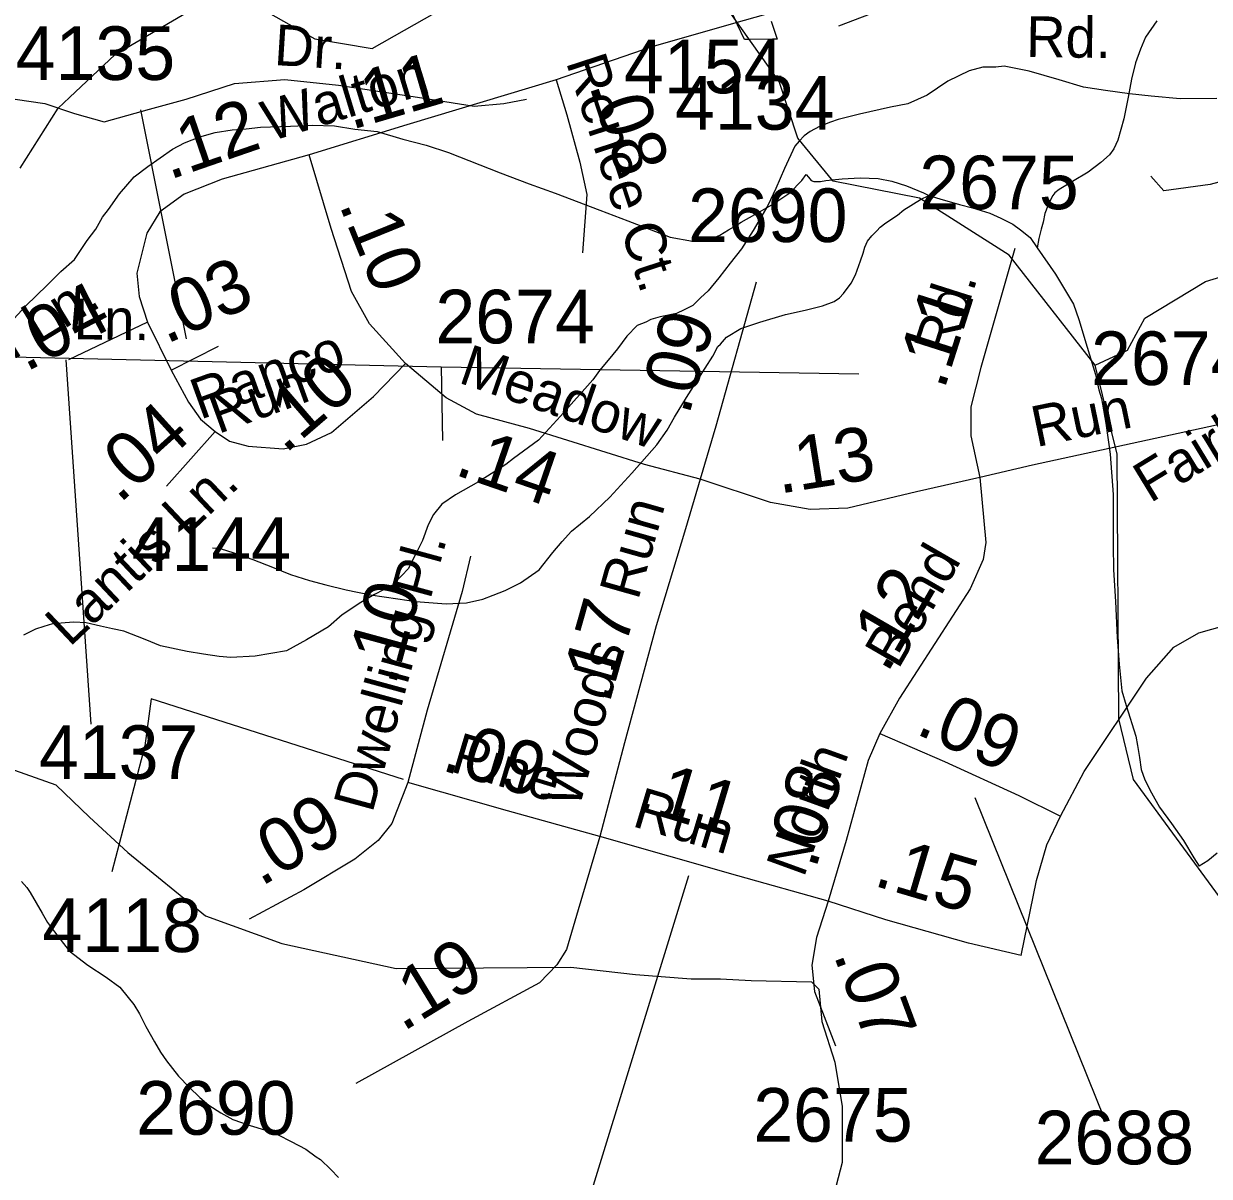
# Model space of a CAD drawing. Extents: x 2169602 to 2449496, y 721995 to 810662.
# Drawn here: x 2398160 to 2400925, y 794793 to 797480 of the extents above; entities that cross this region are included whole.
import ezdxf

# ---------------------------------------------------------------- set-up
doc = ezdxf.new("R2010")
doc.units = 0
doc.layers.add('Default', color=7, linetype='Continuous')

msp = doc.modelspace()

# ---------------------------------------------------------------- linework, layer by layer
at = {"layer": 'Default'}
for p, q in [((2398539.8, 796745.2), (2398433, 797279.2)), ((2397196.1, 796724.9), (2399133.5, 796680.2)), ((2398258.2, 796696.7), (2398316.5, 795847.2)), ((2400378.4, 795676.5), (2400680.4, 794926.3)), ((2399710.5, 795493.6), (2399326.2, 794249.2))]:
    msp.add_line(p, q, dxfattribs=at)
for points in [[(2398266.3, 797307.9), (2398373, 797408.5), (2398605.1, 797544.9), (2398705, 797519.8), (2398839.1, 797444.9), (2398972.2, 797422.5), (2399147.1, 797520.7), (2399338, 797556.1), (2399504.1, 797674.1), (2399686.2, 797942.7), (2399826, 798251.5), (2400025.1, 798427.8), (2400174, 798503.5), (2400406.1, 798761.2), (2400505.2, 798946.2), (2400662, 799103.7), (2400836.1, 799398.6), (2400883.4, 799504.9)], [(2400658.9, 796684.1), (2400457.9, 796940.8), (2400249, 797073), (2400048, 797113.2), (2399965, 797213.3), (2399921.9, 797345.4), (2399721, 797628.4), (2399577, 797952.9), (2399568, 798103.9), (2399432, 798592.2), (2399421, 799094.3)], [(2401076, 797995), (2401022.2, 797916.5), (2400976.2, 797854.1), (2400879.3, 797790.9), (2400754.9, 797754.7), (2400429.4, 797653.6), (2399840.3, 797487.1), (2399624.7, 797426.4), (2399401.8, 797348.9)], [(2400409.8, 797609.5), (2400303.8, 797567.7), (2400060.4, 797474)], [(2399903, 797486.2), (2399917, 797443.7), (2399906.5, 797443.6), (2399854, 797442.9), (2399841, 797443.1), (2399825, 797477.7), (2399792.2, 797551.2)], [(2399903, 797486.2), (2399917, 797443.7), (2399906.5, 797443.6), (2399854, 797442.9), (2399841, 797443.1), (2399825, 797477.7), (2399792.2, 797551.2)], [(2400802.6, 797486.7), (2400776.6, 797448.9), (2400764.7, 797420.6), (2400753, 797388.8), (2400743.3, 797350.5), (2400735.6, 797308.7), (2400725.9, 797258.6), (2400712, 797208.4), (2400702.3, 797188.4), (2400692.3, 797174.4), (2400672.2, 797156.4), (2400642.7, 797134.1), (2400606.2, 797112), (2400574.8, 797093.6), (2400565, 797085.8), (2400560.4, 797079.6), (2400554.5, 797069.5), (2400548.8, 797055.4)], [(2400942.9, 797305.6), (2400857, 797305.2), (2400789.2, 797311), (2400739.1, 797316.6), (2400683.1, 797324.2), (2400631.3, 797332.1), (2400575.1, 797349.5), (2400504.7, 797369), (2400446.9, 797381.1), (2400427, 797378.8), (2400396.7, 797378.5), (2400365.1, 797370.3), (2400315.3, 797346.2), (2400267.3, 797313.7), (2400221.6, 797293.5), (2400181.4, 797285.3), (2400109.4, 797269), (2400059.8, 797256.7), (2400041.7, 797250.4), (2400015.9, 797240.6), (2399994, 797228.5), (2399979.8, 797218.4), (2399968.1, 797206.4), (2399958.1, 797194.2), (2399934.5, 797142.1), (2399914.4, 797096.1), (2399895.1, 797056), (2399861.1, 796997.9), (2399833.6, 796955.4), (2399807.6, 796921.6), (2399781.5, 796887.4), (2399756.1, 796857.2), (2399738.1, 796840.8), (2399720.2, 796822.9), (2399700.3, 796812.9), (2399682.3, 796804.6), (2399644.6, 796796.6), (2399622.6, 796790.6), (2399610.5, 796784.3), (2399590.6, 796776.3), (2399566.8, 796751.9), (2399544.9, 796722), (2399523.2, 796695.7), (2399502.9, 796671.5), (2399487.5, 796649.5), (2399411.8, 796565.3), (2399360.4, 796509), (2399302.3, 796466.6), (2399284.7, 796452.6), (2399256.6, 796434.6), (2399220.9, 796412), (2399167, 796382), (2399134.8, 796359.7), (2399115.5, 796335.5)], [(2397390.5, 797368.8), (2397476.7, 797327), (2397565.3, 797272.8), (2397612.1, 797258), (2397697.9, 797234.7), (2397813.4, 797238), (2397951.9, 797277.6), (2398050.9, 797297.5), (2398140, 797304.1), (2398209.2, 797294.1), (2398278.5, 797271), (2398347.8, 797251.2), (2398453.3, 797280.9), (2398539.1, 797304.1), (2398651.3, 797340.4), (2398768.7, 797350.3), (2398894, 797337.1), (2399088.7, 797307.4), (2399210.7, 797287.5), (2399280, 797294.1), (2399332.8, 797304.1)], [(2399401.8, 797348.9), (2399053.4, 797244.2), (2398825.3, 797174.1)], [(2399401.8, 797348.9), (2399426.4, 797267.2), (2399456.8, 797157.3), (2399473.5, 797081.9), (2399463, 796945.8)], [(2402253.8, 797323.8), (2402181.6, 797267.2), (2402069.6, 797203.4), (2401921, 797151), (2401586.7, 797054.7), (2401406.7, 797006.5), (2401343.9, 796991.9), (2401295.8, 796997.1), (2401285.3, 797032.7), (2401278, 797117.5), (2401271.7, 797156.3), (2401253.9, 797181.4), (2401225.7, 797179.3), (2401168.1, 797169.9), (2400926.9, 797104.9), (2400819.2, 797090.3), (2400788.8, 797124.8)], [(2398151.3, 797143.3), (2398240.2, 797283.3), (2398266.3, 797307.9)], [(2398127.1, 796782), (2398164.8, 796822.1), (2398214.6, 796870.5), (2398246.2, 796902.6), (2398278.2, 796930.7), (2398307.9, 796974.9), (2398328, 797001), (2398343.8, 797029), (2398357.8, 797047.2), (2398383.4, 797083.1), (2398417.2, 797123.4), (2398449, 797147.4), (2398506.6, 797187.8), (2398534.5, 797202.2), (2398570.4, 797216.3), (2398606.5, 797226.2), (2398646.3, 797232.8), (2398678.5, 797234.8), (2398712.3, 797239), (2398782.4, 797241.4), (2398832.5, 797243.5), (2398884.6, 797242.1), (2398932.5, 797234.1), (2398984.4, 797228.7), (2399044.3, 797211.1), (2399098.6, 797197.2), (2399150.9, 797179.6), (2399270.9, 797132.2), (2399338.9, 797106.6), (2399399.4, 797084.8), (2399503.4, 797045.5), (2399569.2, 797020.2), (2399667.6, 796982.6), (2399719.9, 796972.7), (2399739.4, 796972.9), (2399765.7, 796979.1), (2399783.5, 796987), (2399793.3, 796993.2), (2399803.4, 796999.4), (2399817.5, 797007.4), (2399833.5, 797017.5), (2399865.1, 797035.5), (2399904.9, 797057.9), (2399946.9, 797085.9), (2399974.6, 797114.2), (2399984.7, 797128.5)], [(2398825.3, 797174.1), (2398622.8, 797117.5), (2398533.9, 797083), (2398477.3, 797041.1), (2398447, 796991.9), (2398424, 796898.7), (2398429.2, 796844.2), (2398448.6, 796784.5)], [(2399050.2, 796688.2), (2398966, 796780.3), (2398924.2, 796855.7), (2398877.1, 797002.3), (2398825.3, 797174.1)], [(2399984.7, 797128.5), (2399990.4, 797122.4), (2399996.8, 797114.5), (2400002.9, 797112.4), (2400018.5, 797112.4), (2400030.8, 797114.7), (2400068.9, 797118.6), (2400111, 797120.8), (2400152.8, 797119.3), (2400184.8, 797113.3), (2400218.6, 797101.7), (2400258.4, 797085.9), (2400271.1, 797079.9)], [(2398600.1, 796258.5), (2398618, 796256.6), (2398650, 796246.9), (2398694.1, 796231.3), (2398740, 796213.4), (2398782.2, 796195.7), (2398826.7, 796182.1), (2398864.5, 796172.3), (2398912.2, 796160.6), (2398968.6, 796148.9), (2399032.4, 796139.2), (2399074.4, 796133.3), (2399144.8, 796127.9), (2399192.3, 796130), (2399230.3, 796138.5), (2399254.5, 796148.2), (2399282.6, 796158.5), (2399318.2, 796176.7), (2399361.9, 796207), (2399393.7, 796247.2), (2399415.4, 796273.1), (2399437.4, 796297.4), (2399479.2, 796331.6), (2399527, 796376), (2399578.4, 796432.2), (2399636.7, 796498.5), (2399660.3, 796532.7), (2399677.9, 796562.8), (2399705.6, 796608.9), (2399727.5, 796642.9), (2399749.3, 796677), (2399767.1, 796705.1), (2399778.8, 796727.3), (2399784.9, 796733.2), (2399798.7, 796749.4), (2399832.7, 796769.4), (2399876.8, 796783.9), (2399936.3, 796802), (2399982.6, 796812.5), (2400022.6, 796822.6), (2400050.1, 796832.7), (2400062.2, 796841), (2400072.2, 796850.8), (2400089.8, 796874.9), (2400100.1, 796894.9), (2400111.8, 796927.2), (2400117.7, 796944.9), (2400121.4, 796959), (2400127.6, 796973.1), (2400137.6, 796985.3), (2400149.3, 796997.4), (2400157.1, 797005.5), (2400171, 797015.6), (2400197.5, 797033.5), (2400212.7, 797045.8), (2400251.2, 797070), (2400271.1, 797079.9)], [(2400271.1, 797079.9), (2400296.9, 797071.9), (2400342.7, 797058.6), (2400372.8, 797050.4), (2400413, 797038.6), (2400439.1, 797026.9), (2400466.9, 797013), (2400485, 796999.3), (2400507.1, 796981.4), (2400523.5, 796957.4)], [(2400548.8, 797055.4), (2400541.2, 797037.5), (2400537.3, 797017.4), (2400533, 797001.4), (2400527.2, 796979.5), (2400523.5, 796957.4)], [(2400658.9, 796684.1), (2400733.9, 796718.6), (2400774.9, 796793.3), (2400916, 796878.9), (2401107.9, 796937.3), (2401167.1, 797030.5)], [(2402601.2, 796979.3), (2402525.8, 796917.5), (2402428.5, 796865.2), (2402260, 796817), (2401715.4, 796707), (2401138.8, 796586.6), (2400512.6, 796450.5), (2400389.6, 796422.2)], [(2400471.8, 796956.3), (2400392.2, 796678.8), (2400369.2, 796586.6), (2400369.2, 796519.6), (2400389.6, 796422.2)], [(2400523.5, 796957.4), (2400566, 796895.8), (2400594.1, 796849.8), (2400608.4, 796826.1), (2400620.7, 796790.2), (2400640.6, 796726.3), (2400659.3, 796662.3), (2400667.3, 796626.2)], [(2399868.5, 796877.7), (2399773.8, 796541.6), (2399737.7, 796418)], [(2398448.6, 796784.5), (2398264.4, 796696.6)], [(2398448.6, 796784.5), (2398504, 796672.5)], [(2398504, 796672.5), (2398613.9, 796728)], [(2398606.1, 796529), (2398639.5, 796507), (2398683.5, 796495.5), (2398765.1, 796489.2), (2398819.5, 796499.7), (2398878.1, 796526.9), (2398975.4, 796610.7), (2399050.2, 796688.2)], [(2399737.7, 796418), (2399607.4, 796452.6), (2399339.6, 796536.4), (2399215.6, 796569.9), (2399145.5, 796607.6), (2399050.2, 796688.2)], [(2398504, 796672.5), (2398543.8, 796598.1), (2398572, 796558.3), (2398606.1, 796529)], [(2399133.5, 796680.2), (2399136.8, 796508.5)], [(2399133.5, 796680.2), (2400107.3, 796663.7)], [(2401167.1, 794204.8), (2401155.9, 794220.1), (2401029, 794652.5), (2400986.9, 794702.5), (2401000.9, 795086.1), (2400949, 795444.7), (2400747.9, 795717.8), (2400714, 795859.6), (2400709.9, 796476.4), (2400658.9, 796684.1)], [(2400667.3, 796626.2), (2400673.4, 796606.6), (2400683.7, 796548.6), (2400694.1, 796476.5), (2400700.7, 796382.6), (2400701.1, 796310.7), (2400700.9, 796264.5), (2400701.5, 796206.8), (2400706.2, 796132.7), (2400710.5, 796048.9), (2400714.6, 795987), (2400721.4, 795924.7), (2400731.5, 795890.8), (2400753.8, 795819.2), (2400757.9, 795797.1), (2400762.2, 795769.3), (2400765.9, 795741.2), (2400774.7, 795717.1), (2400790.5, 795687.1), (2400808.8, 795653.6), (2400836.9, 795615.6), (2400864.9, 795575.7), (2400889.3, 795535.9), (2400901.4, 795516.2)], [(2398606.1, 796529), (2398493, 796402.3)], [(2399737.7, 796418), (2399703.2, 796302.8), (2399634.6, 796076.7), (2399561.4, 795803.4), (2399503.3, 795585.6)], [(2400389.6, 796422.2), (2400242.1, 796388.7), (2400082, 796351), (2399994.1, 796347.9), (2399902, 796363.6), (2399737.7, 796418)], [(2400389.6, 796422.2), (2400403.7, 796270.4), (2400397.5, 796230.6), (2400367.1, 796162.5), (2400202.3, 795908.1), (2400156.8, 795825.4)], [(2399115.5, 796335.5), (2399103.4, 796311.7), (2399089.9, 796275.6), (2399075.7, 796247.3), (2399056.3, 796209.3), (2399042.1, 796193.3), (2399020.2, 796171), (2398978.1, 796149), (2398946.1, 796130.7), (2398902.9, 796102.3), (2398870.9, 796074.3), (2398819.2, 796044), (2398773.1, 796017.7), (2398699.3, 796005.3), (2398643.1, 796002.9), (2398615.4, 796005), (2398579.5, 796010.5), (2398541.4, 796016.6), (2398479, 796030.1), (2398443.2, 796044.1), (2398393.3, 796063.8), (2398366.9, 796069.4), (2398338.6, 796075.3), (2398305.2, 796083.2), (2398276.9, 796085), (2398226.8, 796080.8), (2398207.1, 796074.5), (2398187, 796068.6), (2398159.2, 796054.2)], [(2399202, 796239), (2399182.1, 796156.2), (2399101, 795879.8), (2399056, 795711.2)], [(2400578, 795632.7), (2400633.4, 795736.4), (2400778.9, 795954.2), (2400842.7, 796026.4), (2400900.8, 796059.9), (2401041, 796099.7), (2401394.7, 796166.7), (2401631.7, 796218)], [(2399045.7, 795718.4), (2398457.4, 795906.3), (2398442.4, 795796.8), (2398365.1, 795502.5)], [(2400156.8, 795825.4), (2400129.1, 795762.5), (2400078.3, 795576.1), (2400035.9, 795434.8)], [(2400156.8, 795825.4), (2400307.5, 795760.4), (2400481.2, 795680.9), (2400578, 795632.7)], [(2398138.7, 795739.7), (2398234.6, 795705.4), (2398313.3, 795630.1), (2398402.3, 795547.9), (2398583.7, 795400.6), (2398761.7, 795335.5), (2399028.6, 795277.3)], [(2399056, 795711.2), (2399018.3, 795615.9), (2398986.9, 795576.1), (2398932.5, 795532.2), (2398813.2, 795461), (2398685.6, 795392.9)], [(2399503.3, 795585.6), (2399288.3, 795645.3), (2399056, 795711.2)], [(2400485.9, 795308.1), (2400522, 795482.9), (2400546.1, 795565.7), (2400578, 795632.7)], [(2399503.3, 795585.6), (2399448.9, 795401.3), (2399425.9, 795321.7), (2399402.9, 795286.1), (2399363.1, 795244.2), (2399195.7, 795154.1), (2398934.1, 795009.6)], [(2400035.9, 795434.8), (2399825.6, 795493.4), (2399503.3, 795585.6)], [(2400943.5, 795546.4), (2400921.3, 795528.2), (2400901.4, 795516.2)], [(2398154.8, 795480.1), (2398166.9, 795466.5), (2398174.7, 795454.4), (2398189, 795430.8), (2398202.8, 795406.8), (2398215.3, 795384.6), (2398231.3, 795362.7), (2398265.5, 795319), (2398309.6, 795285.1), (2398351.8, 795257.6), (2398384, 795233.7), (2398403.7, 795210), (2398416.4, 795193.9), (2398430.2, 795172), (2398444.3, 795142.3), (2398464.8, 795106.3), (2398478.5, 795082.3), (2398493.1, 795062.3), (2398521.2, 795026.4), (2398545.4, 795000.8), (2398571, 794976.7), (2398591.5, 794959), (2398619.6, 794941.4), (2398647.5, 794925.4), (2398687.7, 794911.6), (2398721.7, 794901.5), (2398753.7, 794889.8), (2398783.5, 794873.9), (2398817.9, 794856.2), (2398841.7, 794838.4), (2398851.7, 794832.4), (2398876.3, 794808.8), (2398894.2, 794790.7)], [(2400035.9, 795434.8), (2400009.3, 795350), (2399997.7, 795285), (2400004, 795224.3), (2400053.2, 795097.6)], [(2400485.9, 795308.1), (2400363.5, 795336.3), (2400170.9, 795390.8), (2400035.9, 795434.8)], [(2399028.6, 795277.3), (2399435.9, 795280.7), (2399586.5, 795263.6), (2399716.5, 795253.3), (2399785, 795253.3), (2399856.9, 795249.9), (2399997.2, 795246.5), (2400014.3, 795229.4), (2400021.2, 795154), (2400051.4, 795059), (2400068.6, 794955.5), (2400069.1, 794825.2), (2400045.1, 794736.2), (2400031.4, 794636.9), (2400041.7, 794530.7), (2400087.8, 794438.6), (2400099.7, 794382.4)]]:
    msp.add_lwpolyline(points, dxfattribs=at)

# ---------------------------------------------------------------- texts
for s, height, rotation, p in [('Rd.', 95, 359.1903, (2400497.4, 797402.6)), ('Dr.', 95, 356.4222, (2398742.3, 797383.8)), ('.11', 125, 16.3535, (2398923.5, 797232.1)), ('Renee Ct.', 95, 288.0547, (2399424.1, 797391)), ('Walton', 95, 16.9836, (2398733.4, 797204.6)), ('.08', 125, 288.0547, (2399477.9, 797336.7)), ('.12', 125, 19.0635, (2398499.2, 797115.5)), ('.10', 125, 292.1024, (2398894.6, 797058.6)), ('.03', 125, 24.1407, (2398491.8, 796732.2)), ('Rd.', 95, 72.3167, (2400324.7, 796698.5)), ('Fairbluff Ln.', 95, 31.3374, (2397771.1, 796474.1)), ('.04', 125, 27.1443, (2398164.5, 796667.2)), ('Ln.', 95, 359.2124, (2398276.2, 796744.5)), ('.11', 125, 72.3167, (2400306.5, 796623.9)), ('.09', 125, 74.4809, (2399711.2, 796564.5)), ('Ranco', 95, 19.9113, (2398571.2, 796556.4)), ('Fairbluff Ln.', 95, 31.3374, (2400787, 796361.3)), ('Meadow', 95, 340.9671, (2399171, 796644.2)), ('.10', 125, 40.7529, (2398769.2, 796475.4)), ('Run', 95, 19.9113, (2398613.2, 796523)), ('Run', 95, 11.6924, (2400521.4, 796492.7)), ('.04', 125, 42.0233, (2398382.9, 796359.4)), ('.13', 125, 9.0591, (2399922, 796384.1)), ('.14', 125, 340.9671, (2399161.4, 796429.9)), ('Lantis Ln.', 95, 43.3734, (2398266.7, 796025.3)), ('Run', 95, 74.138, (2399592.7, 796134)), ('Dwelling Pl.', 95, 74.7887, (2398972.9, 795638.1)), ('Bend', 95, 59.9405, (2400199.4, 795972.9)), ('.12', 125, 59.9405, (2400173.3, 795963)), ('.10', 125, 74.7887, (2399026.5, 795934.5)), ('.17', 125, 74.138, (2399525.1, 795891.6)), ('Woods', 95, 74.138, (2399454.3, 795646.9)), ('.09', 125, 336.4723, (2400236.7, 795826)), ('.09', 125, 343.2443, (2399131, 795740.8)), ('Pine', 95, 343.2443, (2399152, 795737.8)), ('North', 95, 70.0384, (2399979, 795487.1)), ('.08', 125, 73.7844, (2400007.1, 795507)), ('.11', 125, 343.3375, (2399584.7, 795650.1)), ('Run', 95, 343.3375, (2399576.3, 795610.1)), ('.09', 125, 30.4813, (2398713, 795467.2)), ('.15', 125, 343.5288, (2400138.8, 795471.7)), ('.19', 125, 31.4554, (2399043.9, 795128.8)), ('.07', 125, 290.4028, (2400048, 795310))]:
    msp.add_text(s, height=height, rotation=rotation, dxfattribs=at).set_placement(p)
for s, p in [('4135', (2398141.2, 797348.9)), ('4154', (2399560, 797317.7)), ('4134', (2399678.8, 797233)), ('2675', (2400248.7, 797047.5)), ('2690', (2399709.4, 796971)), ('2674', (2399120, 796734.8)), ('2674', (2400649.2, 796637.6)), ('4144', (2398411.4, 796204.5)), ('4137', (2398195.4, 795719.4)), ('4118', (2398203.6, 795315.8)), ('2690', (2398422.1, 794890)), ('2675', (2399861.4, 794873.8)), ('2688', (2400517.6, 794821))]:
    msp.add_text(s, height=125, dxfattribs=at).set_placement(p)

doc.saveas('drawing.dxf')
